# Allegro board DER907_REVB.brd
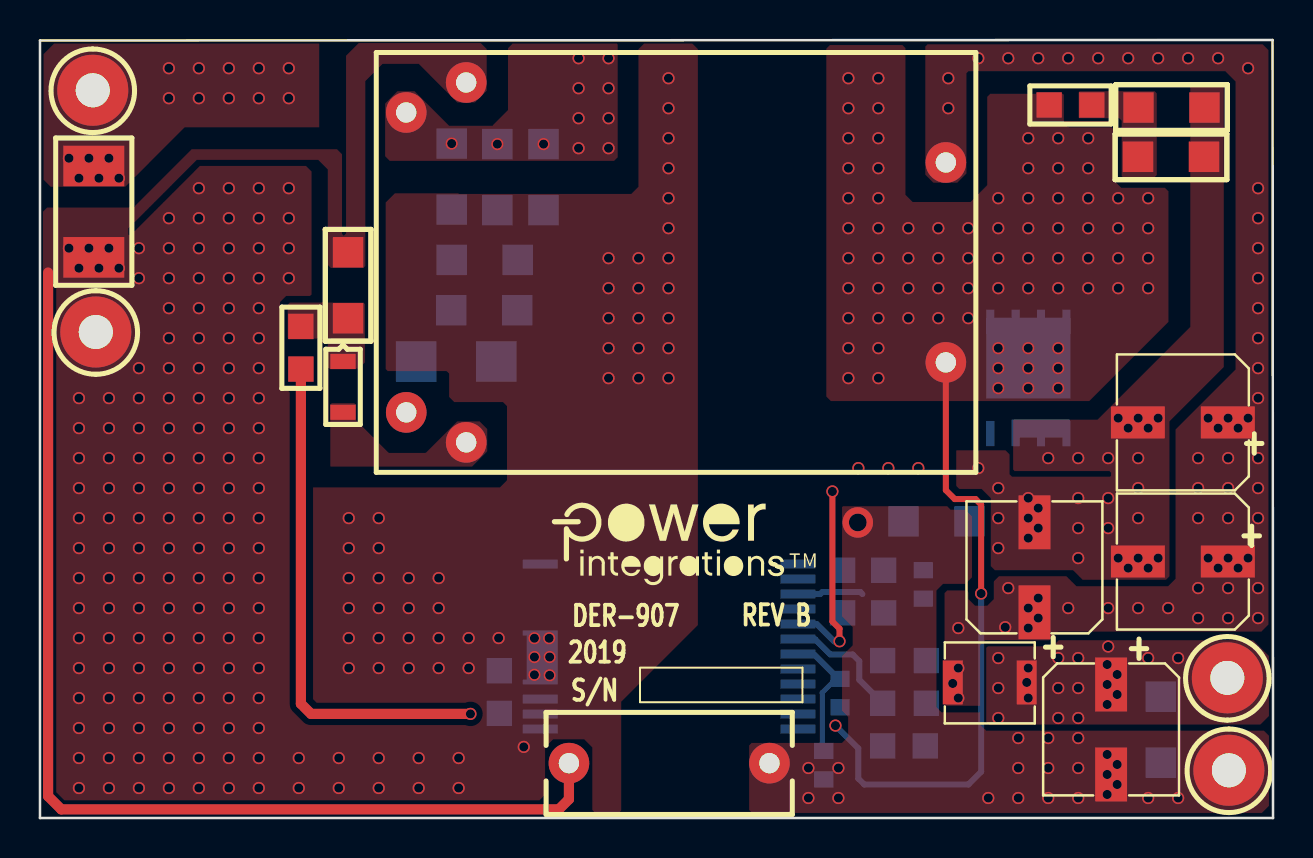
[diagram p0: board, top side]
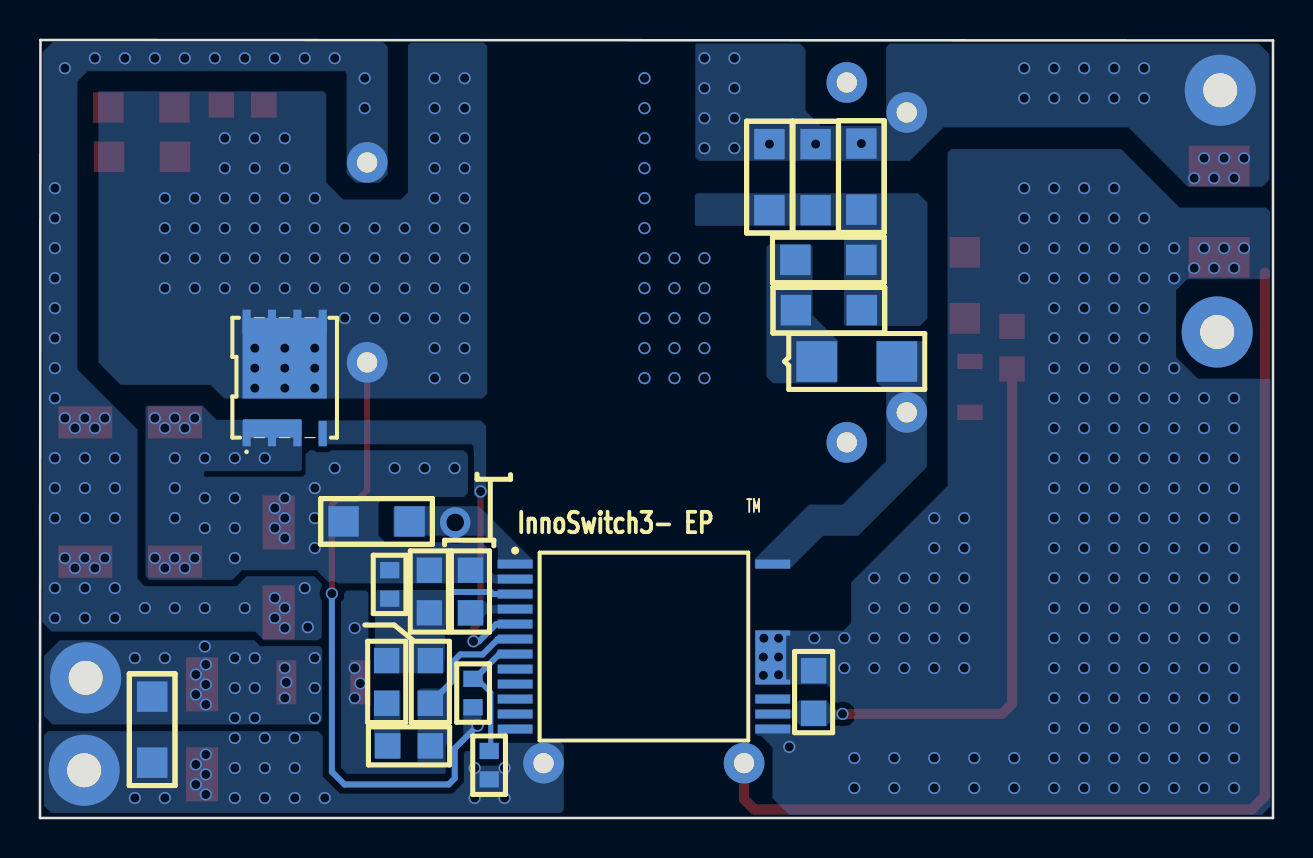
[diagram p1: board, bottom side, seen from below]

Outline 61.7 x 38.91 mm; copper layers: TOP, VCC, GND, BOTTOM. Coordinates in mm from the lower left corner of the outline.
Outline path: 0,38.89 0,0 61.7,0 61.67,38.91 0,38.89

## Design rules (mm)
constraint set DEFAULT: min track width 0.508

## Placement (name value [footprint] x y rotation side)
C1  47 nF  [PISMC1812]  2.69 32.61 270 top
C2  4.7 nF  [PISMC1206]  20.6 33.73 270 bottom
C3  22 uF  [PISMC1206]  15.42 24.99 90 top
C4  0.47 uF  [PISMC0805]  22.99 5.23 90 bottom
C5  2.2 nF  [PISMC0805]  50.5 35.66 0 top
C6  2.2 uF  [PISMC0805]  40.16 12.4 270 bottom
C7  330 pF  [PISMC0603]  44.2 12.4 270 bottom
C8  10 nF  [PISMC0805]  44.35 5.74 90 bottom
C9  220 uF  [PISMCUCC_F80ALELECT]  59.44 19.79 180 top
C10  220 uF  [PISMCUCC_F80ALELECT]  59.44 12.83 180 top
C11  220 uF  [PISMCUCC_F80ALELECT]  49.76 10.29 90 top
C13  100 uF  [PISMCUCC_F80ALELECT]  53.59 6.68 270 top
C14  1 uF  [PISMC1206]  56.08 6.07 270 bottom
C15  2.2 nF  [PI_NP475X200LS395D040]  26.47 2.74 0 top
C16  330 pF  [PISMC0603]  39.22 3.35 270 bottom
D1  US1M-13-F  [PISMDSMA]  22.83 22.83 180 bottom
D2  BAS21HT1G  [PISMSOD323]  15.16 22.83 270 top
L1  SRP4020TA-1R5M  [PI_SM_2-SMD]  47.52 6.78 0 top
NOREF  -  []  25.63 16.21 0 top
NOREF#2  -  []  0 38.89 0 top
NOREF#3  -  []  -232.99 -146.61 0 top
NOREF#4  -  []  -155.18 49.41 0 top
NOREF#5  -  []  61.67 38.91 270 top
Q1  SQJ454EP-T1_GE3  [PISMPQFN5X6B]  51.36 19.23 180 bottom
R1  100 k  [PISMR1206]  22.89 33.71 270 bottom
R2  100 k  [PISMR1206]  25.2 33.71 270 bottom
R3  82  [PISMR1206]  20.57 25.4 0 bottom
R4  82  [PISMR1206]  20.6 27.91 0 bottom
R5  12.1 k  [PISMR0805]  13.06 24.59 270 top
R6  100  [PISMR0603]  40.03 5.54 90 bottom
R7  20  [PISMR1206]  54.97 35.53 0 top
R8  20  [PISMR1206]  54.94 33.07 0 top
R9  11.8 k  [PISMR0805]  42.21 10.26 90 bottom
R10  100 k  [PISMR0805]  42.16 5.74 90 bottom
R11  15 k  [PISMR0805]  42.16 3.61 0 bottom
R12  0.011  [PISMR1206]  46.51 14.83 180 bottom
RTN  BLK  [PITPKEYSTONE125X125]  59.49 2.39 0 top
T1  Planar_TRF  [PI_PLANARXFRMR_30W_PAYTON]  31.83 27.79 270 top
U1  INN3977CQ  [PI_IC_INSOP_24D]  37.92 12.7 180 bottom
VIN+  RED  [PITPKEYSTONE125X125]  2.64 36.4 0 top
VIN-  BLK  [PITPKEYSTONE125X125]  2.79 24.31 0 top
VO  RED  [PITPKEYSTONE125X125]  59.41 7.01 0 top

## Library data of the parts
C1-C6 C8 C14-C16 = CAP NP
C7 = CAP NP: alternate symbols: (pismc0603_1)
C9-C11 C13 = CAP POL
D1 = DIODE
D2 = DIODE: alternate symbols: (pismsod323_1)
L1 = INDUCTOR
Q1 = FET_N_SGD_123_4_5678
R1-R12 = R
RTN VIN+ VIN- VO = TESTPOINT
T1 = PlanarXfrmr_30W_Payton_6
U1 = Inno3CP_3

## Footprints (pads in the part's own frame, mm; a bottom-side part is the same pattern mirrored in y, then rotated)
PI_IC_INSOP_24D
  rect 1.75x0.45 smd: 1(0,0) 2(0,-0.75) 3(0,-1.5) 4(0,-2.25) 5(0,-3) 6(0,-3.75) 7(0,-4.5) 8(0,-5.25) 9(0,-6) 10(0,-6.75) 11(0,-7.5) 12(0,-8.25) 13(12.89,-8.25) 14(12.89,-7.5) 15(12.89,-6.75) 24(12.89,0)
  custom 0.437x0.437 smd: 16(12.89,-4.67)
PI_NP475X200LS395D040
  round 2.032 hole 1.016: 1(0,0) 2(10.033,0)
PI_PLANARXFRMR_30W_PAYTON
  round 2.032 hole 1.016: 1(-9,-10.5) 2(-7.5,-13.5) 3(7.5,-13.5) 4(9,-10.5) 5(5,13.5) 6(-5,13.5)
PI_SM_2-SMD
  rect 1x2.2 smd: 1(-1.85,0) 2(1.85,0)
PISMC0603
  rect 0.813x0.965 smd: 1(0,0) 2(1.422,0)
PISMC0805
  rect 1.27x1.27 smd: 1(0,0) 2(2.134,0)
PISMC1206
  rect 1.524x1.524 smd: 1(0,0) 2(3.302,0)
PISMC1812
  rect 2.032x3.048 smd: 1(0,0) 2(4.572,0)
PISMCUCC_F80ALELECT
  rect 2.7x1.6 smd: 1(0,0) 2(4.5,0)
PISMDSMA
  rect 2.032x2.032 smd: 1(0,0) 2(4.013,0)
PISMPQFN5X6B
  rect 0.406x1.27 smd: 1(0,0) 2(1.27,0) 3(2.54,0) 4(3.81,0)
  rect 0.406x1.219 smd: 5(3.81,5.588) 6(2.54,5.588) 7(1.27,5.588) 8(0,5.588)
PISMR0603
  rect 0.813x0.965 smd: 1(0,0) 2(1.422,0)
PISMR0805
  rect 1.27x1.27 smd: 1(0,0) 2(2.134,0)
PISMR1206
  rect 1.524x1.524 smd: 1(0,0) 2(3.302,0)
PISMSOD323
  rect 0.762x1.27 smd: 1(0,0) 2(2.54,0)
PITPKEYSTONE125X125
  round 3.556 hole 1.702: 1(0,0)

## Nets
GND: C1.2 C3.2 C4.2 C15.1 T1.1 U1.13(VPIN) U1.16 VIN-.1
GND SIGNAL: C13.2 C14.2 C15.2 C16.2 R12.2 RTN.1 U1.1
DRAIN: D1.2 T1.3 U1.24
NC8: U1.8
NC9: U1.9
NC10: U1.10
NC11: U1.11
NC12: U1.12
NC15: U1.15
VO: C9.1 C10.1 C11.1 L1.1 R10.1 R11.1 T1.6 U1.6
N37213: C1.1 C2.1 R1.1 R2.1 T1.2 VIN+.1
N37461: C5.2 R7.1 R8.1
N37469: C6.1 C7.1 C9.2 C10.2 C11.2 Q1.1 Q1.2 Q1.3(S3) R7.2 R8.2 R9.2 R12.1 U1.2
N38055: C3.1 D2.1 R5.1
N38181: C16.1 R6.2 U1.7
N38189: C4.1 R5.2 U1.14
N51802: C13.1 C14.1 L1.2 VO.1
N100534: C2.2 R1.2 R2.2 R3.1 R4.1
N100538: D1.1 R3.2 R4.2
N101873: D2.2 T1.4
N103221: C5.1 Q1.5 Q1.6 Q1.7 Q1.8 R6.1 T1.5
N108532: C6.2 U1.4
N108749: C7.2 C8.2 R9.1 R10.2 U1.3
N109833: C8.1 R11.2
N115689: Q1.4 U1.5

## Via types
v1: diameter 0.61, hole 0.457, TOP to BOTTOM, 437 vias
v2: diameter 1.524, hole 0.889, TOP to BOTTOM, 1 via

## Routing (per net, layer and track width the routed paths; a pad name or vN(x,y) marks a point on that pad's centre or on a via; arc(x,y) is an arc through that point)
GND: length 54.5
  TOP w0.508: C15.1 26.47,0.94 25.96,0.43 1.07,0.43 0.41,1.09 0.41,27.28
  vias: v1(1.45,28.5) v1(1.95,27.5) v1(1.95,21) v1(1.95,19.5) v1(1.95,18) v1(1.95,16.5) v1(1.95,15) v1(1.95,13.5) v1(1.95,12) v1(1.95,10.5) v1(1.95,9) v1(1.95,7.5) v1(1.95,6) v1(1.95,4.5) v1(1.95,3) v1(1.95,1.5) v1(2.45,28.5) v1(2.95,27.5) v1(3.45,28.5) v1(3.45,21) v1(3.45,19.5) v1(3.45,18) v1(3.45,16.5) v1(3.45,15) v1(3.45,13.5) v1(3.45,12) v1(3.45,10.5) v1(3.45,9) v1(3.45,7.5) v1(3.45,6) v1(3.45,4.5) v1(3.45,3) v1(3.45,1.5) v1(3.95,27.5) v1(4.95,28.5) v1(4.95,27) v1(4.95,22.5) v1(4.95,21) v1(4.95,19.5) v1(4.95,18) v1(4.95,16.5) v1(4.95,15) v1(4.95,13.5) v1(4.95,12) v1(4.95,10.5) v1(4.95,9) v1(4.95,7.5) v1(4.95,6) v1(4.95,4.5) v1(4.95,3) v1(4.95,1.5) v1(6.45,30) v1(6.45,28.5) v1(6.45,27) v1(6.45,25.5) v1(6.45,24) v1(6.45,22.5) v1(6.45,21) v1(6.45,19.5) v1(6.45,18) v1(6.45,16.5) v1(6.45,15) v1(6.45,13.5) v1(6.45,12) v1(6.45,10.5) v1(6.45,9) v1(6.45,7.5) v1(6.45,6) v1(6.45,4.5) v1(6.45,3) v1(6.45,1.5) v1(7.95,31.5) v1(7.95,30) v1(7.95,28.5) v1(7.95,27) v1(7.95,25.5) v1(7.95,24) v1(7.95,22.5) v1(7.95,21) v1(7.95,19.5) v1(7.95,18) v1(7.95,16.5) v1(7.95,15) v1(7.95,13.5) v1(7.95,12) v1(7.95,10.5) v1(7.95,9) v1(7.95,7.5) v1(7.95,6) v1(7.95,4.5) v1(7.95,3) v1(7.95,1.5) v1(9.45,31.5) v1(9.45,30) v1(9.45,28.5) v1(9.45,27) v1(9.45,25.5) v1(9.45,24) v1(9.45,22.5) v1(9.45,21) v1(9.45,19.5) v1(9.45,18) v1(9.45,16.5) v1(9.45,15) v1(9.45,13.5) v1(9.45,12) v1(9.45,10.5) v1(9.45,9) v1(9.45,7.5) v1(9.45,6) v1(9.45,4.5) v1(9.45,3) v1(9.45,1.5) v1(10.95,31.5) v1(10.95,30) v1(10.95,28.5) v1(10.95,27) v1(10.95,25.5) v1(10.95,24) v1(10.95,22.5) v1(10.95,21) v1(10.95,19.5) v1(10.95,18) v1(10.95,16.5) v1(10.95,15) v1(10.95,13.5) v1(10.95,12) v1(10.95,10.5) v1(10.95,9) v1(10.95,7.5) v1(10.95,6) v1(10.95,4.5) v1(10.95,3) v1(10.95,1.5) v1(12.45,31.5) v1(12.45,30) v1(12.45,28.5) v1(12.45,27) v1(12.95,3) v1(12.95,1.5) v1(14.95,3) v1(14.95,1.5) v1(15.45,15) v1(15.45,13.5) v1(15.45,12) v1(15.45,10.5) v1(15.45,9) v1(15.45,7.5) v1(16.95,15) v1(16.95,13.5) v1(16.95,12) v1(16.95,10.5) v1(16.95,9) v1(16.95,7.5) v1(16.95,3) v1(16.95,1.5) v1(18.45,12) v1(18.45,10.5) v1(18.45,9) v1(18.45,7.5) v1(18.95,3) v1(18.95,1.5) v1(19.95,12) v1(19.95,10.5) v1(19.95,9) v1(19.95,7.5) v1(20.95,3) v1(20.95,1.5) v1(21.45,9) v1(21.45,7.5) v1(22.95,9) v1(24.21,3.56) v1(24.74,8.99) v1(24.74,8.05) v1(24.74,7.16) v1(25.48,8.99) v1(25.5,8.05) v1(25.5,7.14) v1(28.45,28) v1(28.45,26.5) v1(28.45,25) v1(28.45,23.5) v1(28.45,22) v1(29.95,28) v1(29.95,26.5) v1(29.95,25) v1(29.95,23.5) v1(29.95,22) v1(31.45,37) v1(31.45,35.5) v1(31.45,34) v1(31.45,32.5) v1(31.45,31) v1(31.45,29.5) v1(31.45,28) v1(31.45,26.5) v1(31.45,25) v1(31.45,23.5) v1(31.45,22)
GND SIGNAL:
  vias: v1(38.45,2.5) v1(38.45,1) v1(39.95,2.5) v1(39.95,1) v1(47.45,1) v1(48.95,4) v1(48.95,2.5) v1(48.95,1) v1(50.45,4) v1(50.45,2.5) v1(50.45,1) v1(51.95,4) v1(51.95,2.5) v1(51.95,1) v1(53.4,3.18) v1(53.4,2.18) v1(53.4,1.18) v1(53.9,2.68) v1(53.9,1.68) v1(55.45,1) v1(56.95,1) v2(40.92,14.78)
VO: length 6.1
  BOTTOM w0.3: U1.6 38.78,8.95 39.55,8.18 40.67,8.18 41,7.85 41,6.91 R10.1
  vias: v1(45.45,37) v1(45.45,35.5) v1(45.67,6.73) v1(45.95,9.5) v1(45.95,7.5) v1(45.95,6) v1(46.95,38) v1(48.3,9.54) v1(48.45,38) v1(48.45,11.5) v1(49.45,10.5) v1(49.45,9.5) v1(49.95,38) v1(49.95,11) v1(49.95,10) v1(51.45,38) v1(51.45,10.5) v1(52.95,38) v1(53.45,10.5) v1(54.45,38) v1(54.95,10.5) v1(55.95,38) v1(56.45,10.5) v1(57.45,38) v1(57.95,18) v1(57.95,16.5) v1(57.95,15) v1(57.95,11.5) v1(57.95,10) v1(58.45,20) v1(58.45,13) v1(58.95,38) v1(58.95,19.5) v1(58.95,12.5) v1(59.45,20) v1(59.45,18) v1(59.45,16.5) v1(59.45,15) v1(59.45,13) v1(59.45,11.5) v1(59.45,10) v1(59.95,19.5) v1(59.95,12.5) v1(60.45,37.5) v1(60.45,20) v1(60.45,13) v1(60.95,31.5) v1(60.95,30) v1(60.95,28.5) v1(60.95,27) v1(60.95,25.5) v1(60.95,24) v1(60.95,22.5) v1(60.95,21) v1(60.95,18) v1(60.95,16.5) v1(60.95,15) v1(60.95,11.5) v1(60.95,10)
N37213:
  vias: v1(1.45,33) v1(1.95,32) v1(2.45,33) v1(2.95,32) v1(3.45,33) v1(3.95,32) v1(6.45,37.5) v1(6.45,36) v1(7.95,37.5) v1(7.95,36) v1(9.45,37.5) v1(9.45,36) v1(10.95,37.5) v1(10.95,36) v1(12.45,37.5) v1(12.45,36) v1(20.6,33.73) v1(22.89,33.71) v1(25.2,33.71) v1(26.95,38) v1(26.95,36.5) v1(26.95,35) v1(26.95,33.5) v1(28.45,38) v1(28.45,36.5) v1(28.45,35) v1(28.45,33.5)
N37469:
  vias: v1(40.95,17.5) v1(42.45,17.5) v1(43.95,17.5) v1(46.95,17.5) v1(47.95,16.5) v1(47.95,15) v1(47.95,13.5) v1(49.45,16) v1(49.45,15) v1(49.45,14) v1(49.95,15.5) v1(49.95,14.5) v1(50.45,18) v1(51.95,18) v1(51.95,16) v1(51.95,14.5) v1(51.95,13) v1(53.45,18) v1(53.45,16) v1(53.45,14.5) v1(53.95,20) v1(53.95,13) v1(54.45,19.5) v1(54.45,12.5) v1(54.95,20) v1(54.95,18) v1(54.95,16.5) v1(54.95,15) v1(54.95,13) v1(55.45,19.5) v1(55.45,12.5) v1(55.95,20) v1(55.95,13)
N38181: length 6.7
  BOTTOM w0.254: C16.1 39.14,3.43 39.14,6.27 39.83,6.96 39.95,6.96
  BOTTOM w0.3: R6.2 39.95,6.96 38.71,8.2 U1.7
N38189: length 25.4
  TOP w0.508: R5.2 13.06,5.71 13.56,5.21 v1(21.54,5.21)
N51802:
  vias: v1(47.95,8) v1(47.95,6.5) v1(47.95,5) v1(49.37,6.78) v1(49.45,7.5) v1(49.45,6) v1(50.95,8) v1(50.95,6.5) v1(50.95,5) v1(51.95,8) v1(51.95,6.5) v1(51.95,5) v1(53.4,7.68) v1(53.4,6.68) v1(53.4,5.68) v1(53.45,8.58) v1(53.9,7.18) v1(53.9,6.18) v1(55.45,8) v1(56.95,8)
N103221: length 31.5
  TOP w0.3: v1(47.09,11.23) 47.09,15.67 46.81,15.95 45.77,15.95 45.33,16.4 T1.5
  BOTTOM w0.3: v1(47.09,11.23) 47.09,2.31 46.46,1.68 41.24,1.68 40.94,1.98 40.94,3.48 v1(39.8,4.62)
  vias: v1(40.45,37) v1(40.45,35.5) v1(40.45,34) v1(40.45,32.5) v1(40.45,31) v1(40.45,29.5) v1(40.45,28) v1(40.45,26.5) v1(40.45,25) v1(40.45,23.5) v1(40.45,22) v1(41.95,37) v1(41.95,35.5) v1(41.95,34) v1(41.95,32.5) v1(41.95,31) v1(41.95,29.5) v1(41.95,28) v1(41.95,26.5) v1(41.95,25) v1(41.95,23.5) v1(41.95,22) v1(43.45,29.5) v1(43.45,28) v1(43.45,26.5) v1(43.45,25) v1(44.95,29.5) v1(44.95,28) v1(44.95,26.5) v1(44.95,25) v1(46.45,29.5) v1(46.45,28) v1(46.45,26.5) v1(46.45,25) v1(47.95,31) v1(47.95,29.5) v1(47.95,28) v1(47.95,26.5) v1(47.95,23.5) v1(47.95,22.5) v1(47.95,21.5) v1(49.45,34) v1(49.45,32.5) v1(49.45,31) v1(49.45,29.5) v1(49.45,28) v1(49.45,26.5) v1(49.45,23.5) v1(49.45,22.5) v1(49.45,21.5) v1(50.95,34) v1(50.95,32.5) v1(50.95,31) v1(50.95,29.5) v1(50.95,28) v1(50.95,26.5) v1(50.95,23.5) v1(50.95,22.5) v1(50.95,21.5) v1(52.45,34) v1(52.45,32.5) v1(52.45,31) v1(52.45,29.5) v1(52.45,28) v1(52.45,26.5) v1(53.95,31) v1(53.95,29.5) v1(53.95,28) v1(53.95,26.5) v1(55.45,31) v1(55.45,29.5) v1(55.45,28) v1(55.45,26.5)
N108749: length 3.3
  BOTTOM w0.3: 41.15,11.2 41.05,11.3 39.14,11.3 39.04,11.2 U1.3
N115689: length 10.1
  TOP w0.3: v1(39.65,16.33) 39.65,9.83 40,9.47 v1(40,8.84)
  BOTTOM w0.3: U1.5 38.86,9.7 39.73,8.84 v1(40,8.84)

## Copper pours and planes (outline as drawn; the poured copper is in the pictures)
GND on TOP: outline of 85 points within 0.15,0.13 32.92,38.76
GND on BOTTOM: 25.91,9.37 21.49,9.37 21.11,9.75 21.11,11.79 16.28,16.61 16.28,26.33 16.29,26.34 16.29,33.27 16.1,33.45 7.59,33.45 4.67,30.53 0.36,30.53 0.15,30.33 0.15,27.1 0.3,26.95 4.29,26.95 4.85,26.39 4.85,23.06 3.76,21.97 0.18,21.97 0.13,21.92 0.13,0.58 0.56,0.15 24.21,0.15 25.04,0.99 25.04,3.53 25.63,4.11 25.78,4.11 25.88,4.22 25.88,4.65 25.86,4.67 24.16,4.67 24.08,4.6 24.08,4.29 23.93,4.14 22.07,4.14 21.91,4.31 21.91,4.53 21.82,4.62 21.21,4.62 20.97,4.86 20.97,5.52 21.16,5.71 21.79,5.71 21.92,5.84 21.92,6.27 22.33,6.68 25.81,6.68 25.91,6.78
GND on VCC, GND: 0.46,22.78 4.11,22.78 4.47,23.14 4.47,26.24 4.52,26.29 4.8,26.29 4.85,26.24 4.85,23.06 4.18,22.39 4.17,22.39 4,22.23 0.28,22.23 0.13,22.07 0.13,0.58 0.56,0.15 24.33,0.15 25.27,1.09 25.27,3.53 25.68,3.94 27.23,3.94 27.64,3.53 27.64,0.41 27.91,0.13 28.83,0.13 29.08,0.38 29.08,5.82 32.92,9.65 32.92,38.46 32.64,38.73 30.23,38.73 29.95,38.46 29.95,30.4 28.98,29.44 27.56,29.44 27.3,29.18 27.3,21.74 26.9,21.34 26.9,17.2 26.47,16.76 20.47,16.76 18.97,18.26 17.45,18.26 16.31,19.41 16.31,22.02 16.64,22.35 20.35,22.35 20.47,22.23 20.47,21.06 20.73,20.8 23.14,20.8 23.37,20.57 23.37,17.86 23.47,17.75 25.83,17.75 25.91,17.83 25.91,21.77 26.29,22.15 26.29,31.11 26.16,31.24 18.31,31.24 16.1,33.45 7.59,33.45 4.67,30.53 0.36,30.53 0.15,30.33 0.15,23.09
GND SIGNAL on TOP: 40.18,15.6 45.39,15.6 45.57,15.42 46.3,15.42 46.63,15.09 46.63,12.04 46.3,11.71 45.19,11.71 44.86,11.38 44.86,5.54 45.11,5.28 47.04,5.28 47.04,4.67 47.35,4.37 61.24,4.37 61.49,4.11 61.49,0.61 61.14,0.25 35.64,0.25 35.48,0.41 35.48,3.63 35.61,3.76 40.13,3.76 40.44,4.06 40.44,5.05 40.13,5.36 40.13,8.1 40.67,8.64 40.67,9.55 40.13,10.08 40.13,15.54
GND SIGNAL on BOTTOM: 43.92,15.6 39.73,15.6 37.06,12.93 37.06,12.5 37.08,12.47 38.73,12.47 38.79,12.52 38.79,13.46 39.45,14.12 44.02,14.12 44.02,15.49
GND SIGNAL on BOTTOM: 35.61,3.76 38.43,3.76 38.43,2.79 38.61,2.62 39.85,2.62 40.03,2.79 40.03,3.28 40.11,3.35 40.39,3.35 40.49,3.25 40.49,1.78 41.05,1.22 46.69,1.22 47.55,2.08 47.55,4.11 47.78,4.34 61.29,4.34 61.49,4.14 61.49,0.61 61.14,0.25 35.64,0.25 35.48,0.41 35.48,3.63
GND SIGNAL on VCC: 35.61,3.76 40.13,3.76 40.44,4.06 40.44,5.05 40.13,5.36 40.13,11.33 40.36,11.56 44.75,11.56 44.93,11.38 44.93,5.61 45.26,5.28 46.99,5.28 47.04,5.23 47.04,4.67 47.4,4.32 61.32,4.32 61.49,4.14 61.49,0.61 61.14,0.25 35.64,0.25 35.48,0.41 35.48,3.63
GND SIGNAL on GND: 35.61,3.76 40.13,3.76 40.44,4.06 40.44,5.05 40.13,5.36 40.13,11.33 40.36,11.56 44.75,11.56 44.96,11.35 44.96,5.59 45.24,5.31 46.94,5.31 47.04,5.21 47.04,4.67 47.4,4.32 61.32,4.32 61.49,4.14 61.49,0.61 61.14,0.25 35.64,0.25 35.48,0.41 35.48,3.63
DRAIN on BOTTOM: 19.35,21.34 19.84,21.82 19.84,23.83 19.81,23.85 17.45,23.85 17.32,23.72 17.32,17.55 20.75,14.12 22.5,14.12 24.16,12.47 25.91,12.47 25.93,12.5 25.93,12.95 23.22,15.67 21.54,15.67 19.35,17.86
VO on TOP: 44.7,31.78 45.9,31.78 46.35,32.23 46.35,37.25 46.46,37.35 59.31,37.35 59.82,36.84 59.82,22.43 56.82,19.43 56.82,11.96 56.45,11.6 51.85,11.6 51.36,12.09 47.98,12.09 47.73,11.84 47.73,10.95 47.4,10.62 46.79,10.62 46.46,10.95 46.46,11.28 46.35,11.38 45.39,11.38 45.26,11.25 45.26,5.71 45.36,5.61 47.04,5.61 47.04,8.64 47.29,8.89 50.5,8.89 50.93,9.32 61.11,9.32 61.47,9.68 61.47,38.4 61.18,38.7 44.41,38.7 44.3,38.58 44.3,32.18
VO on BOTTOM: 44.7,31.78 45.9,31.78 46.35,32.23 46.35,37.25 46.46,37.35 59.31,37.35 59.82,36.84 59.82,22.43 59.82,22.43 56.82,19.43 56.82,11.96 56.45,11.6 51.85,11.6 51.36,12.09 47.98,12.09 47.6,11.71 47.6,9.04 47.75,8.89 50.5,8.89 50.93,9.32 61.11,9.32 61.57,9.78 61.57,38.3 61.06,38.81 44.53,38.81 44.3,38.58 44.3,32.18
VO on BOTTOM: 46.35,11.38 45.39,11.38 45.26,11.25 45.26,2.67 45.14,2.54 42.88,2.54 42.8,2.62 42.8,6.35 42.67,6.48 41.53,6.48 41.33,6.27 41.33,2.34 41.45,2.21 46.33,2.21 46.63,2.51 46.63,10.82 46.48,10.97 46.48,11.25
VO on VCC: 44.7,31.78 45.9,31.78 46.35,32.23 46.35,37.25 46.46,37.35 59.31,37.35 59.82,36.84 59.82,22.43 59.82,22.43 56.82,19.43 56.82,11.96 56.45,11.6 51.85,11.6 51.36,12.09 47.98,12.09 47.73,11.84 47.73,11 47.35,10.62 46.76,10.62 46.48,10.9 46.48,11.3 46.41,11.38 45.39,11.38 45.26,11.25 45.26,5.71 45.36,5.61 46.94,5.61 47.04,5.71 47.04,8.64 47.29,8.89 50.5,8.89 50.93,9.32 61.11,9.32 61.57,9.78 61.57,38.3 61.06,38.81 44.53,38.81 44.3,38.58 44.3,32.18
VO on GND: 44.7,31.78 45.9,31.78 46.35,32.23 46.35,37.25 46.46,37.35 59.31,37.35 59.82,36.84 59.82,22.43 56.82,19.43 56.82,11.96 56.45,11.6 51.85,11.6 51.36,12.09 47.98,12.09 47.69,11.8 47.69,10.91 47.4,10.62 46.84,10.62 46.48,10.97 46.48,11.25 46.35,11.38 45.39,11.38 45.26,11.25 45.26,5.71 45.36,5.61 46.08,5.61 46.09,5.63 46.1,5.61 47.07,5.61 47.17,5.71 47.17,8.64 47.42,8.89 50.5,8.89 50.93,9.32 61.11,9.32 61.57,9.78 61.57,38.3 61.06,38.81 44.53,38.81 44.3,38.58 44.3,32.18
N37213 on TOP: 0.53,31.57 4.27,31.57 7.24,34.54 13.97,34.54 13.97,38.73 0.71,38.73 0.18,38.2 0.18,31.93
N37213 on TOP: 17.88,36.35 18.75,36.35 20.47,34.62 22.66,34.62 22.66,34.65 23.42,35.41 23.42,38.51 23.65,38.73 28.85,38.73 28.91,38.68 28.91,33.05 28.73,32.87 17.5,32.87 17.27,33.1 17.27,35.74
N37213 on BOTTOM, VCC, GND: 0.53,31.57 4.27,31.57 7.24,34.54 16.48,34.54 18.16,32.87 28.73,32.87 28.91,33.05 28.91,38.68 28.85,38.73 23.67,38.73 23.39,38.46 23.39,35.38 22.63,34.62 19.61,34.62 19.35,34.87 19.35,38.56 19.18,38.73 0.71,38.73 0.18,38.2 0.18,31.93
N37461 on TOP: 52.02,36.35 55.78,36.35 55.88,36.25 55.88,32.16 55.75,32.03 54.2,32.03 54.13,32.11 54.13,34.87 54,35 51.99,35 51.97,35.03 51.97,36.3
N37469 on BOTTOM (solid shape): 51.54,19.02 48.62,19.02 48.62,19.94 51.54,19.94
N37469 on TOP: 57.66,36.73 59.16,36.73 59.23,36.65 59.23,22.56 56.52,19.84 56.52,12.09 56.34,11.91 52.17,11.91 51.69,12.4 47.78,12.4 47.57,12.6 47.57,16 47.12,16.46 46,16.46 45.85,16.61 45.85,18.39 48.31,18.39 48.51,18.19 48.51,17.2 48.64,17.07 53.54,17.07 53.59,17.12 53.59,17.27 53.52,17.35 48.77,17.35 48.69,17.42 48.69,19.91 48.72,19.92 52.91,19.92 57.56,24.56 57.56,36.63
N37469 on BOTTOM: 48.59,19.91 52.86,19.91 53.57,20.62 56.34,20.62 56.41,20.55 56.41,12.09 56.24,11.91 52.07,11.91 51.59,12.4 47.93,12.4 47.27,11.73 37.13,11.73 37.06,11.81 37.06,12.09 37.13,12.17 38.96,12.17 39.12,12.32 39.12,13.34 39.57,13.79 44.42,13.79 44.75,14.12 44.75,15.75 44.45,16.05 40.49,16.05 40.28,16.26 40.28,18.19 40.49,18.39 48.21,18.39 48.41,18.19 48.41,17.2 48.54,17.07 53.44,17.07 53.49,17.12 53.49,17.27 53.42,17.35 48.67,17.35 48.59,17.42
N37469 on VCC: 48.59,19.91 52.86,19.91 53.57,20.62 56.34,20.62 56.41,20.55 56.41,12.09 56.24,11.91 52.07,11.91 51.59,12.4 47.83,12.4 47.32,11.89 39.95,11.89 39.65,12.19 39.65,13.79 44.42,13.79 44.75,14.12 44.75,15.75 44.45,16.05 40.49,16.05 40.28,16.26 40.28,16.59 40.03,16.84 39.5,16.84 39.37,16.97 39.37,19.61 39.65,19.89 48.23,19.89 48.41,19.71 48.41,17.2 48.54,17.07 53.44,17.07 53.49,17.12 53.49,17.27 53.42,17.35 48.67,17.35 48.59,17.42
N37469 on GND: 48.59,19.91 52.86,19.91 53.57,20.62 56.34,20.62 56.41,20.55 56.41,12.09 56.24,11.91 52.07,11.91 51.59,12.4 47.83,12.4 47.32,11.89 39.95,11.89 39.65,12.19 39.65,13.79 44.42,13.79 44.75,14.12 44.75,15.75 44.45,16.05 40.49,16.05 40.28,16.26 40.28,16.59 39.9,16.97 39.37,16.97 39.37,19.61 39.65,19.89 48.23,19.89 48.41,19.71 48.41,17.2 48.54,17.07 53.44,17.07 53.49,17.12 53.49,17.27 53.42,17.35 48.67,17.35 48.59,17.42
N38055 on TOP: 16.18,25.78 16.26,25.7 16.26,22.78 15.95,22.48 14.45,22.48 14.4,22.53 14.4,23.8 14.45,23.85 14.58,23.85 14.6,23.88 14.6,23.95 14.58,23.98 12.45,23.98 12.4,24.03 12.4,25.68 12.5,25.78
N38189 on BOTTOM: 21.29,5.49 21.95,5.49 22.35,5.89 23.7,5.89 24.16,5.44 25.88,5.44 25.88,4.98 24,4.98 23.62,4.6 22.35,4.6 22.05,4.9 21.34,4.9 21.23,5 21.23,5.44
N51802 on TOP: 47.42,8.59 50.67,8.59 50.98,8.89 60.71,8.89 61.49,8.1 61.49,5.11 61.06,4.67 47.47,4.67 47.35,4.8 47.35,8.51
N51802 on BOTTOM: 50.67,8.59 50.98,8.89 60.71,8.89 61.49,8.1 61.49,5.11 61.06,4.67 47.75,4.67 47.75,4.7 47.57,4.88 47.57,8.46 47.7,8.59
N51802 on VCC: 50.67,8.59 50.98,8.89 60.71,8.89 61.49,8.1 61.49,5.11 61.06,4.67 47.47,4.67 47.35,4.8 47.35,8.51 47.42,8.59
N51802 on GND: 50.67,8.59 50.98,8.89 60.71,8.89 61.49,8.1 61.49,5.11 61.06,4.67 47.68,4.67 47.47,4.88 47.47,8.48 47.57,8.59
N100534 on BOTTOM: 17.75,31.24 17.3,30.78 17.3,24.97 17.65,24.61 21.39,24.61 21.46,24.69 21.46,29.26 21.82,29.62 28.85,29.62 28.93,29.69 28.93,31.14 28.83,31.24
N100538 on BOTTOM: 23.16,28.7 25.2,28.7 25.35,28.55 25.35,22.07 25.02,21.74 21.87,21.74 21.77,21.84 21.77,23.88 23.04,25.15 23.04,28.57
N101873 on TOP: 22,19.84 20.88,19.84 19.3,18.26 17.45,18.26 15.8,19.91 15.8,20.68 15.72,20.75 14.6,20.75 14.53,20.68 14.53,17.6 14.55,17.58 21.62,17.58 22.38,18.34 22.38,19.46
N103221 on BOTTOM (solid shape): 51.56,20.98 47.35,20.98 47.35,25.02 51.56,25.02
N103221 on TOP: 43.15,38.66 43.31,38.51 43.31,31.17 43.66,30.81 46.56,30.81 47.4,31.65 47.4,36.07 47.55,36.22 51.18,36.22 51.23,36.17 51.23,34.8 51.49,34.54 53.62,34.54 53.8,34.37 53.8,31.83 54.1,31.52 56.29,31.52 56.46,31.34 56.46,24.82 52.5,20.85 39.57,20.85 39.34,21.08 39.34,38.48 39.52,38.66
N103221 on BOTTOM: 39.93,4.32 39.67,4.32 39.6,4.39 39.6,5.92 40.49,5.92 40.51,5.89 40.51,4.04 40.49,4.01 40.23,4.01
N103221 on BOTTOM, VCC, GND: 39.55,20.98 52.48,20.98 53.16,21.67 57.66,21.67 58.78,22.78 58.78,36.3 58.72,36.35 47.52,36.35 47.37,36.2 47.37,31.78 46.53,30.94 43.64,30.94 43.28,31.29 43.28,38.63 43.13,38.79 39.5,38.79 39.32,38.61 39.32,21.21
N108532 on BOTTOM: 37.08,10.64 39.24,10.64 39.5,10.9 40.61,10.9 40.69,10.82 40.69,9.73 40.59,9.63 39.73,9.63 39.52,9.83 39.52,10.03 39.32,10.24 37.08,10.24
N108749 on BOTTOM: 44.81,11.4 44.93,11.28 44.93,8.59 44.96,8.56 44.96,7.34 44.86,7.24 41.55,7.24 41.43,7.37 41.43,9.65 41.38,9.7 41.38,10.74 41.05,11.07 41.05,11.35 41.1,11.4
N109833 on BOTTOM: 43.71,6.38 44.93,6.38 44.98,6.32 44.98,3.02 44.93,2.97 43.71,2.97 43.66,3.02 43.66,6.32
N115689 on BOTTOM: 47.7,19.89 39.65,19.89 39.37,19.61 39.37,16.15 39.5,16.03 39.85,16.03 40,16.18 40,18.59 40.11,18.69 47.78,18.69 47.78,19.81

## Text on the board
Ref Des/Silkscreen Bottom: TM | InnoSwitch3- EP
Ref Des/Silkscreen Top: 2019 | S/N | DER-907 | REV B
User.5: 14.  FAB HOUSE LOGO,DATE CODE TO BE IN SILK SCREEN ONLY.DO NOT USE COPPER. | 13.  MATERIAL FR4 COPPER 2oz THICKNESS 0.062" | 0.  FOUR LAYER BOARD. TOP,VCC,GND,BOTTOM. | PLEASE DELETE THESE PINS
User.9: FIGURE | FINISHED_SIZE | 18.0 | 35.0 | 40.0 | 67.0 | DRILL CHART: TOP to BOTTOM | ALL UNITS ARE IN MILS | TOLERANCE_DRILL | +3.0/-3.0 | +0.0/-0.0 | PLATED | QTY | 437 | 1 | 2 | 6 | 4
